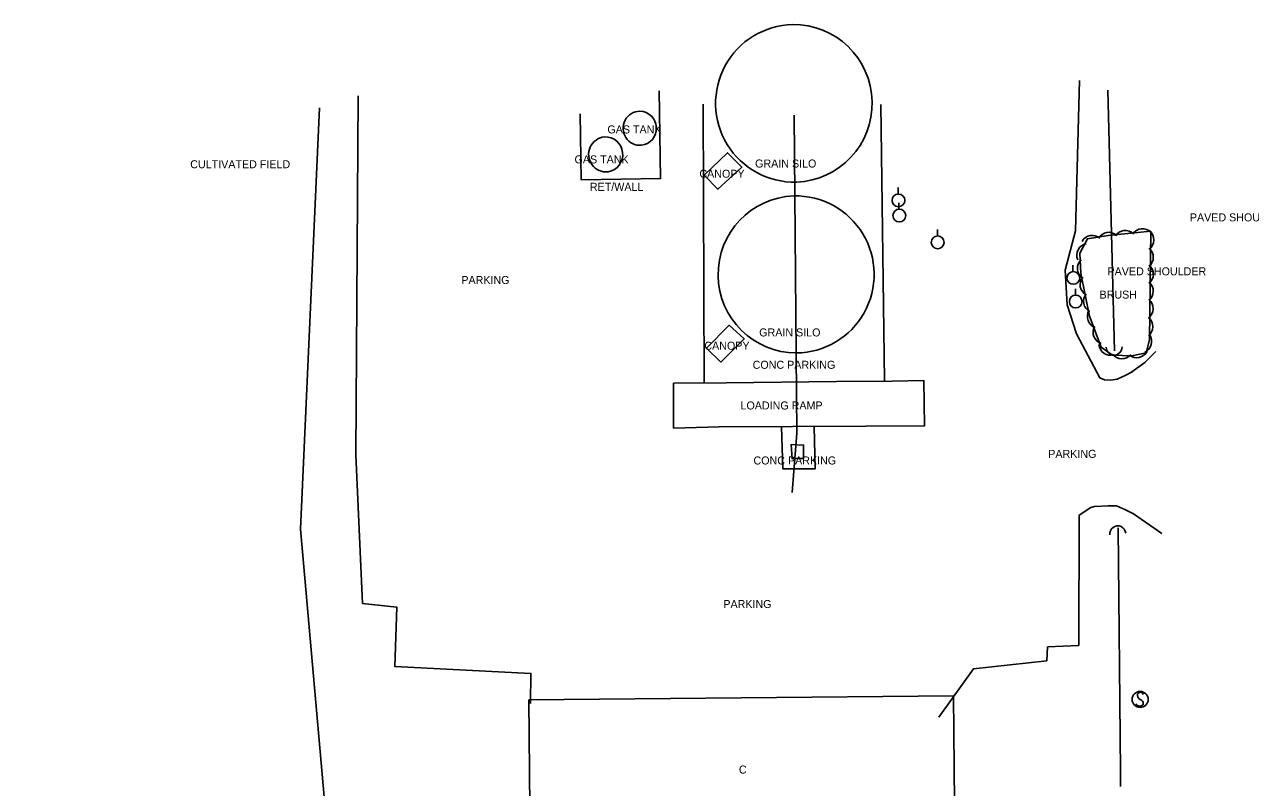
# Model space of a CAD drawing. Extents: x 1802180 to 1804859, y 572524 to 575172.
# Drawn here: x 1803146.7 to 1803529.6, y 574934.3 to 575172.4 of the extents above; entities that cross this region are included whole.
import ezdxf

# ---------------------------------------------------------------- set-up
doc = ezdxf.new("R2010")
doc.units = 0
for name, color, linetype in [('S_BUILDING', 7, 'Continuous'), ('S_BUILDING_ANNOT', 7, 'Continuous'), ('S_CROSS_DRAIN', 7, 'Continuous'), ('S_MISC_BOUNDARY', 7, 'Continuous'), ('S_MISC_BOUNDARY_ANNOT', 7, 'Continuous'), ('S_MISC_STRUCTURES', 7, 'Continuous'), ('S_MISC_STRUCTURES_ANNOT', 7, 'Continuous'), ('S_PARKING', 7, 'Continuous'), ('S_PARKING_ANNOT', 7, 'Continuous'), ('S_SHOULDER_ANNOT', 7, 'Continuous'), ('S_SIGN', 7, 'Continuous'), ('S_STREAM', 7, 'Continuous'), ('S_TREE', 7, 'Continuous'), ('S_TREE_ANNOT', 7, 'Continuous'), ('S_UTILITY_POLE', 7, 'Continuous'), ('S_WALL', 7, 'Continuous'), ('S_WALL_ANNOT', 7, 'Continuous')]:
    doc.layers.add(name, color=color, linetype=linetype)

msp = doc.modelspace()

# ---------------------------------------------------------------- linework, layer by layer
at = {"layer": 'S_BUILDING'}
msp.add_lwpolyline([(1803304.17, 574961.62), (1803436.84, 574962.91), (1803437.28, 574918.07), (1803304.61, 574916.78), (1803304.17, 574961.62)], dxfattribs=at)
at = {"layer": 'S_CROSS_DRAIN'}
for centre, start, end in [((1803487.03, 575071.75), 181.3138, 1.643), ((1803488.17, 575013.41), 6.0322, 186.3613)]:
    msp.add_arc(centre, 2.5, start, end, dxfattribs=at)
at = {"layer": 'S_MISC_BOUNDARY'}
msp.add_lwpolyline([(1803238.85, 575146.42), (1803232.86, 575014.91), (1803244.4, 574885.46), (1803146.7, 574886.86)], dxfattribs=at)
at = {"layer": 'S_MISC_STRUCTURES'}
for points in [[(1803387.06, 575144.11), (1803387.97, 575044.81), (1803386.45, 575026.37)], [(1803363.27, 575120.97), (1803370.77, 575127.9), (1803366.3, 575132.38), (1803359.01, 575125.36), (1803363.27, 575120.97), (1803363.31, 575120.97)], [(1803364.16, 575067.03), (1803371.48, 575074.29), (1803366.78, 575078.54), (1803359.7, 575071.42), (1803364.16, 575067.03), (1803364.4, 575067.2)], [(1803349.43, 575060.43), (1803365.85, 575060.59), (1803400.36, 575061.01), (1803417.71, 575061.06), (1803427.6, 575061.25), (1803427.84, 575047.15), (1803409.62, 575047.06), (1803363.67, 575046.87), (1803349.43, 575046.46), (1803349.43, 575060.43), (1803349.44, 575060.49)], [(1803386.43, 575036.94), (1803389.97, 575036.99), (1803390.05, 575041.14), (1803386.11, 575041.29), (1803386.43, 575036.94), (1803386.47, 575036.94)]]:
    msp.add_lwpolyline(points, dxfattribs=at)
for centre, radius, start, end in [((1803387.15, 575147.81), 24.6, 91.3909, 271.4687), ((1803386.85, 575147.81), 24.61, 272.1662, 90.6934), ((1803338.73, 575140.02), 5.35, 276.8683, 88.0655)]:
    msp.add_arc(centre, radius, start, end, dxfattribs=at)
for centre, major_axis, ratio, start_param, end_param in [((1803338.99, 575140.03), (0.23, -5.33), 0.999754, 3.114758, 6.31002), ((1803328.38, 575131.89), (4.23, -3.49), 0.998423, 2.350717, 5.517875), ((1803328.06, 575131.86), (-3.93, 3.84), 0.998099, 2.520164, 5.517408), ((1803387.84, 575094.4), (5.98, -23.78), 0.999964, 2.929585, 6.034783), ((1803387.55, 575094.4), (-17.73, -16.93), 0.999997, 0.818214, 3.973018)]:
    msp.add_ellipse(centre, major_axis=major_axis, ratio=ratio, start_param=start_param, end_param=end_param, dxfattribs=at)
at = {"layer": 'S_PARKING'}
for p, q in [((1803358.98, 575060.79), (1803358.71, 575147.53)), ((1803414.13, 575147.47), (1803415.28, 575061.3))]:
    msp.add_line(p, q, dxfattribs=at)
for points in [[(1803476.17, 575154.92), (1803474.91, 575107.98), (1803471.78, 575095.76), (1803472.31, 575084.96), (1803475.25, 575075.86), (1803482.59, 575062.1), (1803483.99, 575061.46), (1803485.92, 575061.4), (1803488, 575061.69), (1803490.67, 575062.92), (1803492.71, 575063.99)], [(1803250.86, 575150.12), (1803250.2, 575038.09), (1803252.28, 574991.73), (1803262.95, 574990.56), (1803262.37, 574972), (1803304.87, 574969.84), (1803304.78, 574960.46)], [(1803492.18, 575063.67), (1803496.61, 575066.9), (1803500.03, 575070.37)], [(1803383.15, 575046.86), (1803383.56, 575033.68), (1803393.65, 575033.77), (1803393.34, 575046.91)], [(1803432.32, 574956.22), (1803443.05, 574971.29), (1803466.01, 574973.79), (1803466.26, 574978.14), (1803475.98, 574978.6), (1803476.11, 575019.31), (1803479.7, 575021.64), (1803480.85, 575021.92), (1803485.13, 575022.21), (1803487.78, 575022.15), (1803490.58, 575020.88), (1803493.03, 575019.67), (1803501.9, 575013.53)]]:
    msp.add_lwpolyline(points, dxfattribs=at)
at = {"layer": 'S_SIGN'}
msp.add_circle((1803495.16, 574961.75), 2.5, dxfattribs=at)
for centre, radius, start, end in [((1803495.84, 574963.08), 1.51, 167.1196, 241.9813), ((1803495.23, 574963.02), 0.952, 16.5258, 156.8957), ((1803494.74, 574960.41), 1.4, 358.6529, 73.7063), ((1803495, 574960.93), 1.28, 204.641, 335.359)]:
    msp.add_arc(centre, radius, start, end, dxfattribs=at)
at = {"layer": 'S_STREAM'}
msp.add_line((1803485.04, 575151.94), (1803487.16, 575070.59), dxfattribs=at)
msp.add_lwpolyline([(1803488.25, 575015.28), (1803489.05, 574939.37), (1803489.04, 574934.51)], dxfattribs=at)
at = {"layer": 'S_TREE'}
msp.add_lwpolyline([(1803498.45, 575107.94), (1803498.08, 575074.04), (1803497.01, 575069.96), (1803492.6, 575068.98), (1803486.55, 575069.16), (1803483.01, 575071.65), (1803479.36, 575081.35), (1803476.64, 575094.65), (1803476.34, 575101.04), (1803478.69, 575105.47), (1803485.21, 575106.59), (1803498.45, 575107.94)], dxfattribs=at)
for centre, start, end in [((1803485.37, 575103.91), 48.956, 150.5529), ((1803490.48, 575104.48), 45.0588, 146.6557), ((1803495.9, 575105.03), 45.0588, 146.6557), ((1803495.75, 575105.14), 308.5752, 50.1721), ((1803479.02, 575100.4), 101.193, 202.7899), ((1803480.17, 575102.94), 48.956, 150.5529), ((1803495.62, 575099.8), 308.5752, 50.1721), ((1803479.2, 575096.2), 131.9304, 233.5273), ((1803495.64, 575094.5), 308.5752, 50.1721), ((1803480.03, 575091.23), 140.7474, 242.3443), ((1803495.61, 575089.18), 308.5752, 50.1721), ((1803481.13, 575086.03), 140.7474, 242.3443), ((1803495.55, 575083.73), 308.5752, 50.1721), ((1803482.3, 575081.32), 149.8299, 251.4268), ((1803495.46, 575078.07), 308.5752, 50.1721), ((1803484.11, 575076.29), 149.8299, 251.4268), ((1803485.92, 575072.82), 184.0604, 285.6573), ((1803495.09, 575073.43), 294.5623, 36.1592), ((1803489.46, 575071.71), 217.5631, 319.16), ((1803494.07, 575072.04), 231.6486, 333.2456)]:
    msp.add_arc(centre, 3.65, start, end, dxfattribs=at)
at = {"layer": 'S_UTILITY_POLE'}
for p, q in [((1803419.54, 575119.52), (1803419.54, 575121.51)), ((1803419.81, 575114.8), (1803419.81, 575116.78)), ((1803431.81, 575106.44), (1803431.81, 575108.42)), ((1803474.17, 575095.34), (1803474.17, 575097.32)), ((1803474.92, 575087.97), (1803474.92, 575089.95))]:
    msp.add_line(p, q, dxfattribs=at)
for centre in [(1803419.66, 575117.51), (1803419.92, 575112.79), (1803431.92, 575104.42), (1803474.28, 575093.32), (1803475.04, 575085.95)]:
    msp.add_circle(centre, 2, dxfattribs=at)
at = {"layer": 'S_WALL'}
msp.add_lwpolyline([(1803320.22, 575144.5), (1803320.56, 575123.97), (1803345.34, 575124.3), (1803344.9, 575151.69)], dxfattribs=at)

# ---------------------------------------------------------------- texts
at = {"layer": 'S_BUILDING_ANNOT'}
msp.add_text('C ', height=2.5, dxfattribs=at).set_placement((1803369.83, 574938.6))
at = {"layer": 'S_MISC_BOUNDARY_ANNOT'}
msp.add_text('CULTIVATED FIELD', height=2.5, dxfattribs=at).set_placement((1803198.46, 575127.55))
at = {"layer": 'S_MISC_STRUCTURES_ANNOT'}
for s, p in [('GAS TANK', (1803328.76, 575138.42)), ('GAS TANK', (1803318.49, 575129.06)), ('GRAIN SILO', (1803374.89, 575127.77)), ('CANOPY', (1803357.48, 575124.59)), ('GRAIN SILO', (1803376.17, 575075.05)), ('CANOPY', (1803359.04, 575070.9)), ('LOADING RAMP', (1803370.33, 575052.25)), ('LOADING RAMP', (1803370.33, 575052.25))]:
    msp.add_text(s, height=2.5, dxfattribs=at).set_placement(p)
at = {"layer": 'S_PARKING_ANNOT'}
for s, p in [('PARKING', (1803283.14, 575091.42)), ('CONC PARKING', (1803374.12, 575064.95)), ('PARKING', (1803466.45, 575037.15)), ('CONC PARKING', (1803374.38, 575035.08)), ('PARKING', (1803364.97, 574990.27))]:
    msp.add_text(s, height=2.5, dxfattribs=at).set_placement(p)
at = {"layer": 'S_SHOULDER_ANNOT'}
for p in [(1803510.68, 575110.96), (1803484.95, 575094.12)]:
    msp.add_text('PAVED SHOULDER', height=2.5, dxfattribs=at).set_placement(p)
at = {"layer": 'S_TREE_ANNOT'}
msp.add_text('BRUSH', height=2.5, dxfattribs=at).set_placement((1803482.46, 575086.86))
msp.add_text('BRUSH', height=2.5, dxfattribs=at).set_placement((1803482.46, 575086.86))
at = {"layer": 'S_WALL_ANNOT'}
msp.add_text('RET/WALL', height=2.5, dxfattribs=at).set_placement((1803323.28, 575120.5))

doc.saveas('drawing.dxf')
